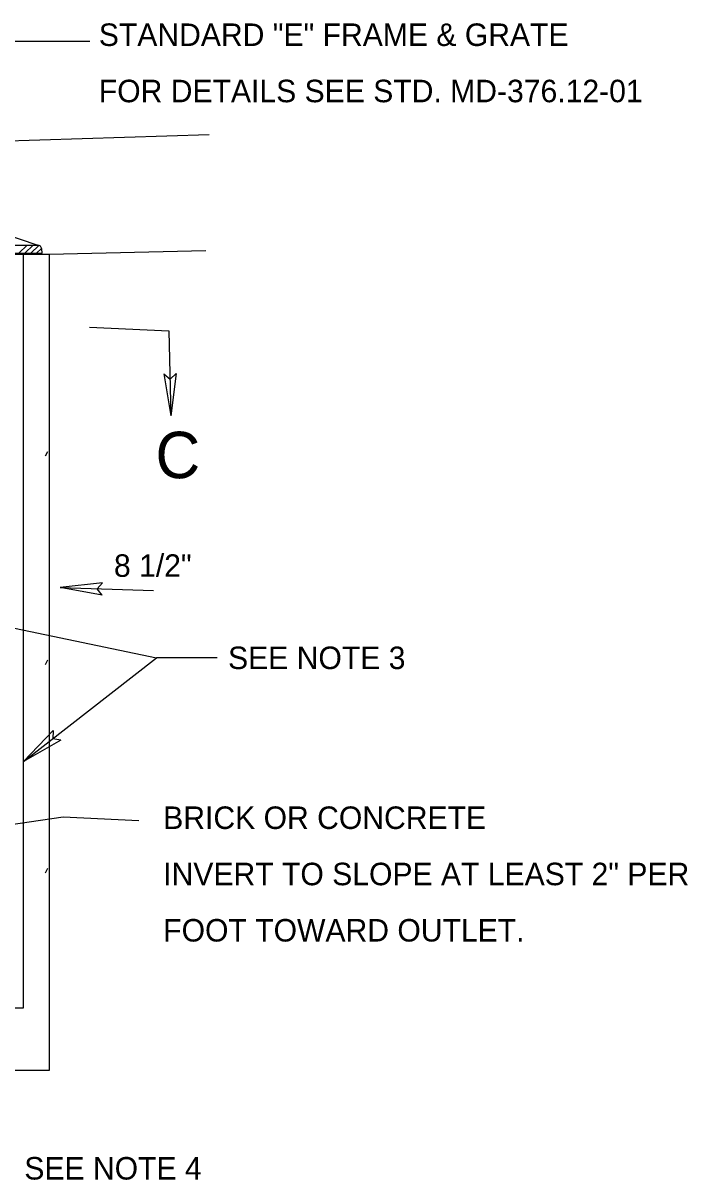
# Model space of a CAD drawing. Extents: x 0.9 to 8.1, y 0.4 to 10.5.
# Drawn here: x 3.714 to 5.131, y 5.144 to 7.61 of the extents above; entities that cross this region are included whole.
import ezdxf

# ---------------------------------------------------------------- set-up
doc = ezdxf.new("R2010")
doc.units = 0
for name, color, linetype in [('DETL-DIMS', 7, 'Continuous'), ('DETL-LINE', 7, 'Continuous'), ('DETL-NOTE', 7, 'Continuous')]:
    doc.layers.add(name, color=color, linetype=linetype)

msp = doc.modelspace()

# ---------------------------------------------------------------- linework, layer by layer
at = {"layer": 'DETL-DIMS'}
for p, q in [((3.8561, 7.5706), (3.5409, 7.5706)), ((3.8557, 6.9619), (4.0249, 6.9539)), ((4.0249, 6.9539), (4.0289, 6.7725)), ((4.0137, 6.8622), (4.0289, 6.7725)), ((4.0137, 6.8622), (4.0272, 6.8512)), ((4.04, 6.8628), (4.0272, 6.8512)), ((4.04, 6.8628), (4.0289, 6.7725)), ((3.8834, 6.4168), (3.793, 6.4064)), ((3.8834, 6.4168), (3.8717, 6.404)), ((3.793, 6.4064), (3.9917, 6.4004)), ((3.8826, 6.3906), (3.793, 6.4064)), ((3.8826, 6.3906), (3.8717, 6.404)), ((4.1274, 6.2566), (3.9981, 6.2566)), ((3.7779, 6.1017), (3.715, 6.036)), ((3.7779, 6.1017), (3.7771, 6.0844)), ((3.7941, 6.081), (3.715, 6.036)), ((3.7941, 6.081), (3.7771, 6.0844)), ((3.3682, 5.8536), (3.7993, 5.9181)), ((3.7993, 5.9181), (3.9604, 5.91))]:
    msp.add_line(p, q, dxfattribs=at)
for points in [[(3.5386, 6.3525), (3.9981, 6.2566)], [(3.715, 6.036), (3.9981, 6.2566)]]:
    msp.add_lwpolyline(points, dxfattribs=at)
at = {"layer": 'DETL-LINE'}
for p, q in [((3.5353, 7.355), (4.1108, 7.3724)), ((3.5421, 7.2043), (3.7476, 7.1361)), ((3.5531, 7.1365), (3.7447, 7.1365)), ((3.7049, 7.1196), (3.7227, 7.1365)), ((3.7175, 7.1196), (3.7353, 7.1365)), ((3.7301, 7.1196), (3.7474, 7.1361)), ((3.7426, 7.1196), (3.7534, 7.1299)), ((3.7544, 7.1196), (3.7535, 7.1288)), ((3.5296, 7.1196), (3.7544, 7.1196)), ((3.715, 5.5104), (3.715, 7.1185)), ((3.7698, 7.1175), (4.1031, 7.1251)), ((3.7615, 6.6873), (3.7664, 6.697)), ((3.7615, 6.2429), (3.7664, 6.2526)), ((3.7615, 5.7985), (3.7664, 5.8081)), ((3.5386, 5.5104), (3.715, 5.5104))]:
    msp.add_line(p, q, dxfattribs=at)
msp.add_lwpolyline([(1.5066, 6.3068), (1.5066, 7.1175), (3.7698, 7.1175), (3.7698, 5.3767), (1.5066, 5.3767), (1.5066, 5.5888)], dxfattribs=at)
msp.add_ellipse((3.7447, 7.1281), major_axis=(0.00889, 0), ratio=0.952381, start_param=0.087266, end_param=1.570796, dxfattribs=at)

# ---------------------------------------------------------------- texts
at = {"layer": 'DETL-NOTE'}
for s, height, p in [('STANDARD "E" FRAME & GRATE ', 0.048, (3.8753, 7.5614)), ('FOR DETAILS SEE STD. MD-376.12-01', 0.048, (3.8753, 7.4414)), ('C', 0.099, (3.996, 6.6398)), ('8 1/2"', 0.048, (3.9076, 6.4295)), ('SEE NOTE 3', 0.048, (4.1508, 6.2328)), ('BRICK OR CONCRETE ', 0.048, (4.0126, 5.8919)), ('INVERT TO SLOPE AT LEAST 2" PER', 0.048, (4.0126, 5.7719)), ('FOOT TOWARD OUTLET.', 0.048, (4.0126, 5.6519)), ('SEE NOTE 4', 0.048, (3.7165, 5.1444))]:
    msp.add_text(s, height=height, dxfattribs=at).set_placement(p)

doc.saveas('drawing.dxf')
